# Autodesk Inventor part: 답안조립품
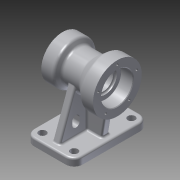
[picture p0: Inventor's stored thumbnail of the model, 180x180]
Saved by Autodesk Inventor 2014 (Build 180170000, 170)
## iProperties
Created: 2015-08
Part Number: 답안조립품
Material: Aluminum 6061
Document SubType Name: Modeling
Designer: user
Density: 2.71 g/cm^3
Appearance: Aluminum - Flat
Mass: 1062.42 g
Surface Area: 750.544 cm^2
Volume: 392.037 cm^3
Author: user
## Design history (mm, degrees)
sketch "Sketch1"
  geometry: L1 (-45, 0)-(45, 0); L2 (45, 0)-(45, 40); L3 (45, 40)-(25, 40); L4 (25, 40)-(8.315, 26); L5 (8.315, 26)-(-19.804, 26); L6 (-19.804, 26)-(-25, 35); L7 (-45, 0)-(-45, 35); L8 (-45, 35)-(-25, 35); 2 further points
  constraints: 16 end point, 3 perpendicular, 1 coincident, 1 horizontal, 1 midpoint, 1 parallel
  dimensions: "d0" = 90 distance of L1.start L1.end; "d1" = 40 distance of L1.end L2.end; "d2" = 20 distance of L2.end L3.end; "d4" = 35 distance of L1.start L7.end; "d5" = 20 distance of L7.end L6.end; "d6" = 40 deg angle of L4 L5; "d7" = 60 deg angle of L5 L6; "d8" = 52 diameter of L5 L1; "d9" = 120 deg angle of L8 L6
revolve "Revolution1" sketch "Sketch1" stored, may be unused: angle "d10" = 90 deg
sketch "Sketch2"
  geometry: C1 r 40 at (0, 0) reference; C2 r 26 at (0, 0)
  constraints: 1 centre point, 1 coincident
  dimensions: "d11" = 52 diameter of C2
extrude "Extrusion1" cut sketch "Sketch2" distance "d12" = 20; taper "d13" = 0 deg
sketch "Sketch3"
  geometry: C1 r 26 at (0, 0) reference; C2 r 19 at (0, 0)
  constraints: 1 centre point, 1 coincident
  dimensions: "d14" = 38 diameter of C2
extrude "Extrusion2" cut sketch "Sketch3" distance "d15" = 3; taper "d16" = 0 deg
sketch "Sketch4"
  geometry: C1 r 35 at (0, 0) reference; C2 r 20 at (0, 0)
  constraints: 1 centre point, 1 coincident
  dimensions: "d17" = 40 diameter of C2
extrude "Extrusion3" cut sketch "Sketch4" distance "d18" = 17; taper "d19" = 0 deg
sketch "Sketch5"
  geometry: C1 r 20 at (0, 0) reference; C2 r 16 at (0, 0)
  constraints: 1 centre point, 1 coincident
  dimensions: "d20" = 32 diameter of C2
extrude "Extrusion4" cut sketch "Sketch5" stored distance "d21" = 17; taper "d22" = 0 deg
sketch "Sketch6"
  geometry: L1 (-33, 0)-(33, 0); C1 r 40 at (0, 0) reference; A1 r 33 centre (0, 0) between (-33, 0) and (33, 0)
  constraints: 2 end point, 2 point on circle, 1 centre point, 1 coincident, 1 horizontal
  dimensions: "d23" = 66 diameter of A1; "d24" = 66 distance of L1.start L1.end
hole "Hole1" sketch "Sketch6" at (-33, 0) diameter "d25" = 3.459; stored, may be unused: countersink angle "d29" = 90 deg, drill point angle "d31" = 118 deg; dims "d26" = 10, "d27" = 4, "d28" = 2, "d30" = 13
pattern_circular "Circular Pattern1" dims angle "d33" = 360 deg
sketch "Sketch7"
  geometry: L1 (27, 0)-(-27, 0); C1 r 35 at (0, 0) reference; A1 r 27 centre (0, 0) between (27, 0) and (-27, 0)
  constraints: 2 end point, 2 point on circle, 1 centre point, 1 coincident, 1 horizontal
  dimensions: "d35" = 54 diameter of A1; "d36" = 54 distance of L1.start L1.end
hole "Hole2" sketch "Sketch7" at (27, 0) diameter "d37" = 3.459; stored, may be unused: countersink angle "d41" = 90 deg, drill point angle "d43" = 118 deg; dims "d38" = 10, "d39" = 4, "d40" = 2, "d42" = 13
pattern_circular "Circular Pattern2" dims angle "d45" = 360 deg
workplane "Work Plane2"
  workplane "Work Plane1"
sketch "Sketch8"
  geometry: L1 (-80, -35)-(-80, 35) reference; L2 (-80, 61)-(0, 61); L3 (0, 61)-(0, -61); L4 (0, -61)-(-80, -61); L5 (-80, -61)-(-80, 61); L6 (-80, 61)-(0, -61); L7 (0, 61)-(-80, -61); 3 further points
  constraints: 12 end point, 4 midpoint, 2 parallel, 1 horizontal, 1 perpendicular
  dimensions: "d48" = 80 distance of L3.end L4.end; "d49" = 122 distance of L2.end L3.end
extrude "Extrusion5" join sketch "Sketch8" distance "d50" = 12; taper "d51" = 0 deg
sketch "Sketch9"
  geometry: L1 (-66, 47)-(-14, 47); L2 (-14, 47)-(-14, -47); L3 (-14, -47)-(-66, -47); L4 (-66, -47)-(-66, 47); L5 (-66, 47)-(-14, -47); L6 (-14, 47)-(-66, -47); L7 (0, 61)-(-80, -61); C1 r 6 at (-66, -47); C2 r 6 at (-14, -47); C3 r 6 at (-66, 47); C4 r 6 at (-14, 47); 3 further points
  constraints: 14 end point, 4 centre point, 4 coincident, 4 midpoint, 2 parallel, 1 horizontal, 1 perpendicular
  dimensions: "d52" = 52 distance of L2.end L3.end; "d53" = 94 distance of L1.end L2.end; "d54" = 12 diameter of C1; "d55" = 12 diameter of C2; "d56" = 12 diameter of C3; "d57" = 12 diameter of C4
extrude "Extrusion6" cut sketch "Sketch9" stored distance "d58" = 12; taper "d59" = 0 deg
workplane "Work Plane4"
  workplane "Work Plane3"
sketch "Sketch10"
  geometry: L1 (0, 0)-(122, 0) reference; L2 (0, 0)-(10, 0); L3 (122, 0)-(112, 0); L4 (112, 0)-(86.091, 71.185); L5 (10, 0)-(35.909, 71.185); C1 r 26 at (61, 78) reference; A1 r 26 centre (61, 78) between (86.091, 71.185) and (35.909, 71.185) reference; 1 further point
  constraints: 8 end point, 2 point on circle, 2 point on line
  dimensions: "d61" = 10 distance of L1.start L2.end; "d62" = 10 distance of L1.end L3.end; "d63" = 70 deg angle of L4 L1; "d64" = 70 deg angle of L5 L1
extrude "Extrusion7" join sketch "Sketch10" stored distance "d65" = 12; taper "d66" = 0 deg
workplane "Work Plane5"
sketch "Sketch11"
  geometry: L1 (0, 12)-(80, 12) reference; L2 (80, 12)-(70, 12); L3 (80, 55)-(60, 55) reference; L4 (0, 12)-(10, 12); L5 (10, 50)-(-10, 50) reference; L6 (10, 12)-(70, 12); L7 (10, 55)-(25.054, 64.918); L8 (25.054, 64.918)-(55.716, 64.918); L9 (55.716, 64.918)-(61.325, 57.401); L10 (61.325, 57.401)-(70, 55); L11 (10, 12)-(2.767, 53.019); L12 (70, 12)-(70, 57.693); L13 (70, 57.693)-(60.476, 57.693); L14 (60.476, 57.693)-(55.716, 64.918); L15 (25.054, 64.918)-(10, 55); L16 (10, 55)-(2.767, 53.019); 1 further point
  constraints: 26 end point, 4 perpendicular, 2 point on line, 1 collinear, 1 midpoint, 1 parallel
  dimensions: "d67" = 10 distance of L1.end L2.end; "d68" = 10 distance of L1.start L4.end; "d71" = 80 deg angle of L1 L11
extrude "Extrusion8" join sketch "Sketch11" stored distance "d72" = 12; taper "d73" = 0 deg
fillet "Fillet1" dims "d74" = 14
fillet "Fillet2" dims "d75" = 3
chamfer "Chamfer1" distance "d76" = 1; stored, may be unused: second distance "d77" = 2, angle "d78" = 45 deg
fillet "Fillet3" dims "d79" = 5
fillet "Fillet4" dims "d80" = 5
fillet "Fillet5" dims "d81" = 5
fillet "Fillet6" dims "d82" = 5
fillet "Fillet7" dims "d83" = 0.3
fillet "Fillet8" dims "d84" = 0.3
fillet "Fillet9" dims "d85" = 3
fillet "Fillet10" dims "d86" = 3
fillet "Fillet11" dims "d87" = 3
fillet "Fillet12" dims "d88" = 3
fillet "Fillet13" dims "d89" = 3
fillet "Fillet14" dims "d90" = 3
fillet "Fillet15" dims "d91" = 3
fillet "Fillet16" dims "d92" = 3
fillet "Fillet17" dims "d93" = 3
fillet "Fillet18" dims "d94" = 3
fillet "Fillet19" dims "d95" = 3
workplane "Work Plane6"
sketch "Sketch12"
  geometry: L1 (-21, 37.119)-(-21, 0) reference; L2 (-28, -3)-(-17, -3) reference; L3 (-17, -3)-(-17, 21); L4 (-21, 21)-(-5, 21); 2 further points
  constraints: 4 end point, 2 perpendicular, 1 coincident, 1 point on line, 1 other
  dimensions: "d96" = 24 distance of L2.end L3.end; "d97" = 16 distance of L4.start L4.end; "d98" = 24 distance between parallel lines of L2 L4
emboss "Emboss1" sketch "Sketch12" dims "d99" = 0.5, "d100" = 0
sketch "Sketch13"
  geometry: L1 (-50.432, 52)-(-3, 52) reference; L2 (-3.521, 64)-(-3.521, 58) reference; L3 (-35.431, 64)-(-3.521, 64) reference; L4 (-3.521, 58)-(-35.431, 58) reference; L5 (-3, 107.716)-(-3, 70) reference; L6 (-63.06, 85.856)-(-3, 107.716) reference; L7 (-3, 70)-(-50.432, 70) reference; L8 (0, 108)-(0, 14) reference; L9 (12, 108)-(12, 14) reference; L10 (12, 61)-(-18, 61); L11 (-12, 85)-(-30, 85); L12 (-12, 37)-(-30, 37); L13 (-24, 91)-(-18, 91); L14 (-24, 79)-(-18, 79); L15 (-24, 43)-(-18, 43); L16 (-24, 31)-(-18, 31); A1 r 6 centre (-35.431, 70) between (-35.626, 64.003) and (-35.431, 64) reference; A2 r 43 centre (-78.521, 61) between (-35.626, 57.997) and (-35.626, 64.003) reference; A3 r 6 centre (-35.431, 52) between (-35.431, 58) and (-35.626, 57.997) reference; A4 r 29 centre (-78, 61) between (-50.432, 70) and (-63.06, 85.856) reference; A5 r 6 centre (-18, 85) between (-18, 79) and (-18, 91); A6 r 6 centre (-24, 85) between (-24, 91) and (-24, 79); A7 r 6 centre (-24, 37) between (-24, 43) and (-24, 31); A8 r 6 centre (-18, 37) between (-18, 31) and (-18, 43)
  constraints: 14 end point, 12 point on circle, 7 parallel, 6 tangent, 4 centre point, 2 point on line, 1 midpoint
  dimensions: "d102" = 30 distance of L10.end L10.start; "d104" = 12 diameter of A5; "d105" = 18 distance of L11.start L11.end; "d106" = 18 distance of L12.start L12.end; "d107" = 6 distance of L13.start L13.end; "d108" = 6 distance of L15.start L15.end; "d109" = 6 distance of L16.start L16.end; "d110" = 48 distance of A8.centre A5.centre; "d111" = 60 distance between parallel lines of L16 L13; "d112" = 9 distance from line of L5 L11.start; "d113" = 15 distance from line of L1 A7.centre
extrude "Extrusion9" cut sketch "Sketch13" stored distance "d114" = 10; taper "d115" = 0 deg
body "Solid1" dims "d100" = 0
node "Projected Loop1"
node "Projected Loop2"
node "Projected Loop3"
other parameters: "d103" = 12
